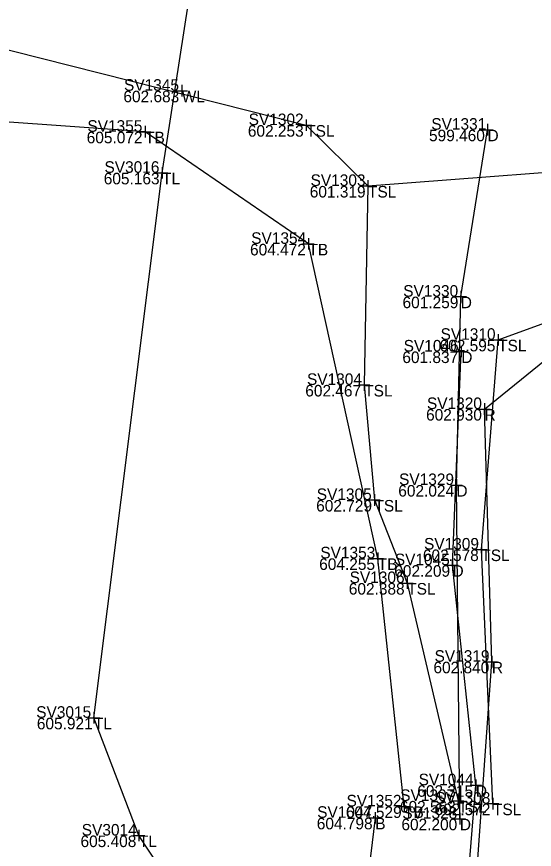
# Model space of a CAD drawing. Extents: x -2 to 1979875, y -2 to 232027.
# Drawn here: x 1978726.83 to 1978749.24, y 231225.36 to 231261.41 of the extents above; entities that cross this region are included whole.
import ezdxf

# ---------------------------------------------------------------- set-up
doc = ezdxf.new("R2010")
doc.units = 0
for name, color, linetype in [('_CIVIL_CONSTRUCTION', 7, 'Continuous'), ('DR_X_Ditch', 7, 'Continuous'), ('DR_X_Erosion_Control', 7, 'Continuous'), ('GE_P_Alignment', 7, 'Continuous'), ('GE_P_Alignment_1000_Curve_Data', 7, 'Continuous'), ('GE_X_Alignment', 7, 'Continuous'), ('GE_X_Alignment_100_Curve_Data', 7, 'Continuous'), ('GE_X_Alignment_100_Stations', 7, 'Continuous'), ('HY_X_Water_Edge', 7, 'Continuous'), ('SV_X_Toe_of_Slope', 7, 'Continuous'), ('SV_X_Top_of_Bank', 7, 'Continuous')]:
    doc.layers.add(name, color=color, linetype=linetype)

msp = doc.modelspace()

# ---------------------------------------------------------------- linework, layer by layer
at = {"layer": 'DR_X_Ditch'}
for points in [[(1978746.015, 231226.682), (1978745.866, 231241.131), (1978746.055, 231249.288), (1978747.211, 231256.517)], [(1978742.253, 231123.729), (1978744.469, 231147.505), (1978746.577, 231170.723), (1978746.925, 231192.27), (1978746.813, 231208.011), (1978745.79, 231216.793), (1978746.707, 231228.131), (1978745.697, 231237.66), (1978746.077, 231246.913)]]:
    msp.add_lwpolyline(points, dxfattribs=at)
at = {"layer": 'DR_X_Erosion_Control'}
msp.add_lwpolyline([(1978754.349, 231247.608), (1978756.246, 231247.151), (1978755.199, 231237.468), (1978752.104, 231223.077), (1978746.455, 231220.249), (1978747.402, 231233.48), (1978747.083, 231244.422), (1978752.039, 231248.449)], close=True, dxfattribs=at)
at = {"layer": 'GE_P_Alignment'}
msp.add_lwpolyline([(1978742.352, 231226.722), (1978740.039, 231207.756), (1978741.585, 231191.589), (1978740.923, 231171.641), (1978739.848, 231152.451), (1978736.877, 231135.037), (1978737.12, 231125.328)], dxfattribs=at)
at = {"layer": 'GE_P_Alignment_1000_Curve_Data'}
msp.add_lwpolyline([(1978737.693, 231077.945), (1978737.389, 231087.473), (1978737.815, 231097.725), (1978739.016, 231107.053), (1978740.421, 231120.833), (1978741.632, 231130.981), (1978742.549, 231144.249), (1978743.532, 231155.069), (1978744.086, 231165.377), (1978744.766, 231176.911), (1978744.147, 231186.88), (1978743.211, 231197.568), (1978741.558, 231207.59), (1978737.988, 231217.051), (1978732.124, 231225.954), (1978730.174, 231231.053), (1978733.125, 231254.651), (1978737.318, 231281.706)], dxfattribs=at)
at = {"layer": 'GE_X_Alignment_100_Curve_Data'}
for p, q in [((1978733.725, 231258.205), (1978734.225, 231258.205)), ((1978733.975, 231258.455), (1978733.975, 231257.955)), ((1978733.975, 231258.205), (1978733.975, 231258.205)), ((1978739.113, 231256.715), (1978739.613, 231256.715)), ((1978739.363, 231256.965), (1978739.363, 231256.465)), ((1978739.363, 231256.715), (1978739.363, 231256.715)), ((1978747.211, 231256.767), (1978747.211, 231256.267)), ((1978732.14, 231256.429), (1978732.64, 231256.429)), ((1978732.39, 231256.679), (1978732.39, 231256.179)), ((1978732.39, 231256.429), (1978732.39, 231256.429)), ((1978746.961, 231256.517), (1978747.461, 231256.517)), ((1978747.211, 231256.517), (1978747.211, 231256.517)), ((1978733.125, 231254.901), (1978733.125, 231254.401)), ((1978732.875, 231254.651), (1978733.375, 231254.651)), ((1978733.125, 231254.651), (1978733.125, 231254.651)), ((1978742.039, 231254.331), (1978742.039, 231253.831)), ((1978741.789, 231254.081), (1978742.289, 231254.081)), ((1978742.039, 231254.081), (1978742.039, 231254.081)), ((1978739.46, 231251.824), (1978739.46, 231251.324)), ((1978739.21, 231251.574), (1978739.71, 231251.574)), ((1978739.46, 231251.574), (1978739.46, 231251.574)), ((1978746.055, 231249.538), (1978746.055, 231249.038)), ((1978745.805, 231249.288), (1978746.305, 231249.288)), ((1978746.055, 231249.288), (1978746.055, 231249.288)), ((1978747.423, 231247.419), (1978747.923, 231247.419)), ((1978747.673, 231247.669), (1978747.673, 231247.169)), ((1978747.673, 231247.419), (1978747.673, 231247.419)), ((1978746.077, 231247.163), (1978746.077, 231246.663)), ((1978745.827, 231246.913), (1978746.327, 231246.913)), ((1978746.077, 231246.913), (1978746.077, 231246.913)), ((1978741.875, 231245.716), (1978741.875, 231245.216)), ((1978741.625, 231245.466), (1978742.125, 231245.466)), ((1978741.875, 231245.466), (1978741.875, 231245.466)), ((1978747.083, 231244.672), (1978747.083, 231244.172)), ((1978746.833, 231244.422), (1978747.333, 231244.422)), ((1978747.083, 231244.422), (1978747.083, 231244.422)), ((1978745.866, 231241.381), (1978745.866, 231240.881)), ((1978745.616, 231241.131), (1978746.116, 231241.131)), ((1978745.866, 231241.131), (1978745.866, 231241.131)), ((1978742.067, 231240.483), (1978742.567, 231240.483)), ((1978742.317, 231240.733), (1978742.317, 231240.233)), ((1978742.317, 231240.483), (1978742.317, 231240.483)), ((1978746.696, 231238.338), (1978747.196, 231238.338)), ((1978746.946, 231238.588), (1978746.946, 231238.088)), ((1978746.946, 231238.338), (1978746.946, 231238.338)), ((1978742.211, 231237.956), (1978742.711, 231237.956)), ((1978742.461, 231238.206), (1978742.461, 231237.706)), ((1978742.461, 231237.956), (1978742.461, 231237.956)), ((1978745.447, 231237.66), (1978745.947, 231237.66)), ((1978745.697, 231237.91), (1978745.697, 231237.41)), ((1978745.697, 231237.66), (1978745.697, 231237.66)), ((1978743.488, 231236.887), (1978743.988, 231236.887)), ((1978743.738, 231237.137), (1978743.738, 231236.637)), ((1978743.738, 231236.887), (1978743.738, 231236.887)), ((1978747.402, 231233.73), (1978747.402, 231233.23)), ((1978747.152, 231233.48), (1978747.652, 231233.48)), ((1978747.402, 231233.48), (1978747.402, 231233.48)), ((1978730.174, 231231.303), (1978730.174, 231230.803)), ((1978729.924, 231231.053), (1978730.424, 231231.053)), ((1978730.174, 231231.053), (1978730.174, 231231.053)), ((1978746.707, 231228.381), (1978746.707, 231227.881)), ((1978746.457, 231228.131), (1978746.957, 231228.131)), ((1978746.707, 231228.131), (1978746.707, 231228.131)), ((1978745.947, 231227.701), (1978745.947, 231227.201)), ((1978747.448, 231227.585), (1978747.448, 231227.085)), ((1978743.35, 231227.215), (1978743.85, 231227.215)), ((1978743.6, 231227.465), (1978743.6, 231226.965)), ((1978743.6, 231227.215), (1978743.6, 231227.215)), ((1978745.697, 231227.451), (1978746.197, 231227.451)), ((1978745.947, 231227.451), (1978745.947, 231227.451)), ((1978747.198, 231227.335), (1978747.698, 231227.335)), ((1978747.448, 231227.335), (1978747.448, 231227.335)), ((1978742.352, 231226.972), (1978742.352, 231226.472)), ((1978746.015, 231226.932), (1978746.015, 231226.432)), ((1978742.102, 231226.722), (1978742.602, 231226.722)), ((1978742.352, 231226.722), (1978742.352, 231226.722)), ((1978745.765, 231226.682), (1978746.265, 231226.682)), ((1978746.015, 231226.682), (1978746.015, 231226.682)), ((1978732.124, 231226.204), (1978732.124, 231225.704)), ((1978731.874, 231225.954), (1978732.374, 231225.954)), ((1978732.124, 231225.954), (1978732.124, 231225.954))]:
    msp.add_line(p, q, dxfattribs=at)
at = {"layer": 'HY_X_Water_Edge'}
msp.add_lwpolyline([(1978710.396, 231262.363), (1978725.371, 231260.246), (1978739.363, 231256.715), (1978742.039, 231254.081), (1978754.512, 231255.046), (1978783.289, 231254.287), (1978787.737, 231256.586), (1978799.967, 231256.811), (1978817.09, 231257.737), (1978832.082, 231262.479)], dxfattribs=at)
at = {"layer": 'SV_X_Toe_of_Slope'}
for points in [[(1978631.824, 231277.19), (1978640.947, 231277.193), (1978647.857, 231282.127), (1978659.868, 231277.693), (1978667.495, 231272.236), (1978672.576, 231269.509), (1978692.09, 231264.447), (1978710.396, 231262.363), (1978725.371, 231260.246), (1978739.363, 231256.715), (1978742.039, 231254.081), (1978741.875, 231245.466), (1978742.317, 231240.483), (1978743.738, 231236.887), (1978745.947, 231227.451)], [(1978747.448, 231227.335), (1978746.946, 231238.338), (1978747.673, 231247.419), (1978754.051, 231249.744), (1978754.902, 231254.833), (1978759.728, 231254.551)]]:
    msp.add_lwpolyline(points, dxfattribs=at)
at = {"layer": 'SV_X_Top_of_Bank'}
msp.add_lwpolyline([(1978743.6, 231227.215), (1978742.461, 231237.956), (1978739.46, 231251.574), (1978732.39, 231256.429), (1978722.837, 231257.109), (1978701.711, 231257.875), (1978681.567, 231257.575), (1978668.738, 231260.724), (1978655.79, 231264.664), (1978646.391, 231266.446), (1978642.99, 231270.526), (1978631.535, 231272.449)], dxfattribs=at)

# ---------------------------------------------------------------- texts
at = {"layer": '_CIVIL_CONSTRUCTION'}
for s, p in [('602.683', (1978731.45, 231257.705)), ('602.253', (1978736.838, 231256.215)), ('605.072', (1978729.862, 231255.929)), ('599.460', (1978744.681, 231256.017)), ('605.163', (1978730.6, 231254.151)), ('601.319', (1978739.518, 231253.581)), ('604.472', (1978736.932, 231251.074)), ('601.259', (1978743.534, 231248.788)), ('602.595', (1978745.138, 231246.919)), ('601.837', (1978743.526, 231246.413)), ('602.467', (1978739.324, 231244.966)), ('602.930', (1978744.553, 231243.922)), ('602.024', (1978743.35, 231240.631)), ('602.729', (1978739.796, 231239.983)), ('602.578', (1978744.416, 231237.838)), ('604.255', (1978739.926, 231237.456)), ('602.209', (1978743.176, 231237.16)), ('602.388', (1978741.208, 231236.387)), ('602.840', (1978744.872, 231232.98)), ('605.921', (1978727.704, 231230.553)), ('602.315', (1978744.172, 231227.631)), ('604.529', (1978741.079, 231226.715)), ('602.563', (1978743.422, 231226.951)), ('602.572', (1978744.92, 231226.835)), ('604.798', (1978739.822, 231226.222)), ('602.200', (1978743.485, 231226.182)), ('605.408', (1978729.594, 231225.454))]:
    msp.add_text(s, height=0.5, dxfattribs=at).set_placement(p)
at = {"layer": 'GE_X_Alignment'}
for s, p in [('SV1345', (1978731.478, 231258.205)), ('SV1302', (1978736.873, 231256.715)), ('SV1355', (1978729.893, 231256.429)), ('SV1331', (1978744.779, 231256.517)), ('SV3016', (1978730.631, 231254.651)), ('SV1303', (1978739.553, 231254.081)), ('SV1354', (1978736.983, 231251.574)), ('SV1330', (1978743.563, 231249.288)), ('SV1310', (1978745.181, 231247.419)), ('SV1046', (1978743.583, 231246.913)), ('SV1304', (1978739.398, 231245.466)), ('SV1320', (1978744.591, 231244.422)), ('SV1329', (1978743.384, 231241.131)), ('SV1305', (1978739.82, 231240.483)), ('SV1309', (1978744.464, 231238.338)), ('SV1353', (1978739.975, 231237.956)), ('SV1045', (1978743.2, 231237.66)), ('SV1306', (1978741.244, 231236.887)), ('SV1319', (1978744.92, 231233.48)), ('SV3015', (1978727.677, 231231.053)), ('SV1044', (1978744.23, 231228.131)), ('SV1307', (1978743.434, 231227.451)), ('SV1352', (1978741.11, 231227.215)), ('SV1308', (1978744.957, 231227.335)), ('SV1047', (1978739.839, 231226.722)), ('SV1328', (1978743.524, 231226.682)), ('SV3014', (1978729.647, 231225.954))]:
    msp.add_text(s, height=0.5, dxfattribs=at).set_placement(p)
at = {"layer": 'GE_X_Alignment_100_Stations'}
for s, p in [('WL', (1978733.975, 231257.705)), ('TSL', (1978739.363, 231256.215)), ('TB', (1978732.39, 231255.929)), ('D', (1978747.211, 231256.017)), ('TL', (1978733.125, 231254.151)), ('TSL', (1978742.039, 231253.581)), ('TB', (1978739.46, 231251.074)), ('D', (1978746.055, 231248.788)), ('TSL', (1978747.673, 231246.919)), ('D', (1978746.077, 231246.413)), ('TSL', (1978741.875, 231244.966)), ('R', (1978747.083, 231243.922)), ('D', (1978745.866, 231240.631)), ('TSL', (1978742.317, 231239.983)), ('TSL', (1978746.946, 231237.838)), ('TB', (1978742.461, 231237.456)), ('D', (1978745.697, 231237.16)), ('TSL', (1978743.738, 231236.387)), ('R', (1978747.402, 231232.98)), ('TL', (1978730.174, 231230.553)), ('D', (1978746.707, 231227.631)), ('TB', (1978743.6, 231226.715)), ('TSL', (1978745.947, 231226.951)), ('TSL', (1978747.448, 231226.835)), ('B', (1978742.352, 231226.222)), ('D', (1978746.015, 231226.182)), ('TL', (1978732.124, 231225.454))]:
    msp.add_text(s, height=0.5, dxfattribs=at).set_placement(p)

doc.saveas('drawing.dxf')
